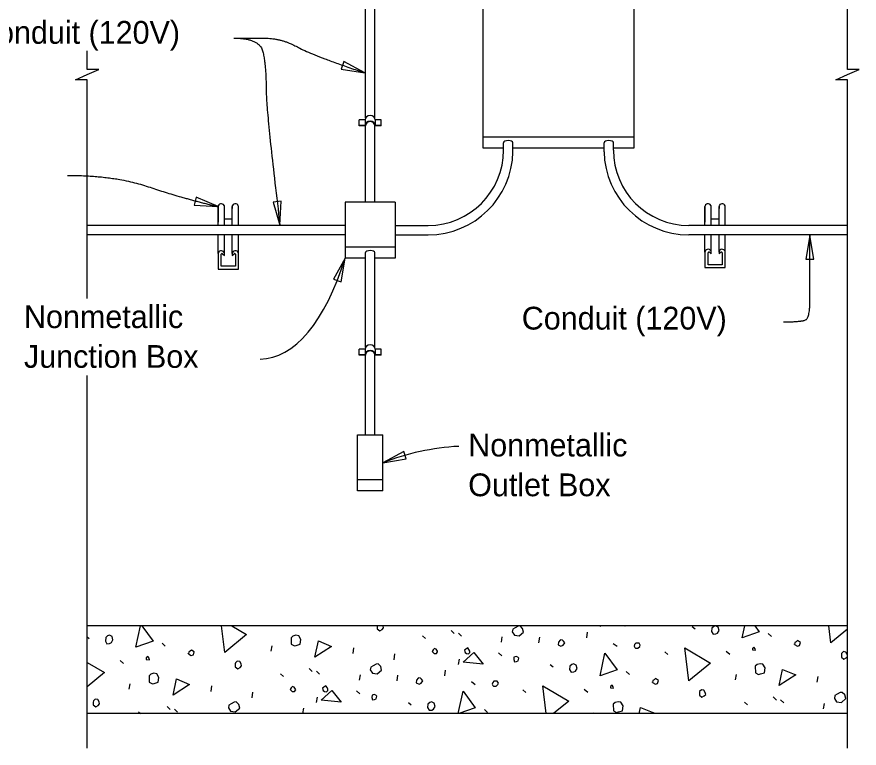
# Model space of a CAD drawing. Extents: x 0 to 30.8, y 0 to 21.2.
# Drawn here: x 12.47 to 18.06, y 9.96 to 14.82 of the extents above; entities that cross this region are included whole.
import ezdxf

# ---------------------------------------------------------------- set-up
doc = ezdxf.new("R2010")
doc.units = 0
for name, color, linetype in [('Dimension', 7, 'Continuous'), ('Lighting', 7, 'Continuous'), ('Miscellaneous', 7, 'Continuous'), ('SteelGirder', 7, 'Continuous'), ('SupstrConc', 7, 'Continuous'), ('TextStructures', 7, 'Continuous')]:
    doc.layers.add(name, color=color, linetype=linetype)

msp = doc.modelspace()

# ---------------------------------------------------------------- linework, layer by layer
at = {"layer": 'Dimension'}
for points in [[(17.9781, 9.9617), (17.9781, 14.3999), (17.9006, 14.3999), (17.9781, 14.4336), (18.0556, 14.4674), (17.9781, 14.4674), (17.9781, 15.572)], [(12.9354, 12.948), (12.9354, 14.3999), (12.8579, 14.3999), (12.9354, 14.4336), (13.0129, 14.4674), (12.9354, 14.4674), (12.9354, 14.5923)], [(12.9354, 9.9617), (12.9354, 12.4363)]]:
    msp.add_lwpolyline(points, dxfattribs=at)
for points in [[(14.7758, 14.445), (14.6363, 14.5201), (14.6193, 14.47)], [(13.8029, 13.5573), (13.6569, 13.6189), (13.6448, 13.5674)], [(14.2135, 13.4344), (14.2209, 13.5927), (14.1684, 13.5863)], [(17.7287, 13.3648), (17.7022, 13.2086), (17.7552, 13.2086)], [(14.6453, 13.2147), (14.5696, 13.0756), (14.6197, 13.0584)], [(14.8953, 11.8557), (15.0516, 11.8817), (15.0343, 11.9317)]]:
    msp.add_lwpolyline(points, close=True, dxfattribs=at)
msp.add_arc((15.4848, 10.3618), 1.606, 93.0575, 111.5329, dxfattribs=at)
msp.add_ellipse((14.0803, 14.1233), major_axis=(-0.0019, 1.5782), ratio=0.437101, start_param=3.141566, end_param=4.098452, dxfattribs=at)
for points in [[(13.9084, 14.676), (14.0798, 14.676), (14.1216, 14.492), (14.1216, 14.1911), (14.2135, 13.4344)], [(13.9084, 14.676), (13.992, 14.676), (14.2219, 14.676), (14.4267, 14.5631), (14.7758, 14.445)], [(12.8048, 13.7647), (13.1183, 13.7647), (13.5572, 13.6152), (13.8029, 13.5573)], [(17.5527, 12.792), (17.6791, 12.792), (17.7287, 12.8218), (17.7287, 13.0474), (17.7287, 13.3648)]]:
    msp.add_open_spline(points, degree=2, dxfattribs=at)
at = {"layer": 'Lighting'}
for p, q in [((14.7808, 14.1436), (14.7808, 14.9071)), ((14.8432, 14.1436), (14.8432, 14.9071)), ((14.7808, 13.5874), (14.7808, 14.0938)), ((14.8432, 13.5874), (14.8432, 14.0938)), ((16.5611, 14.0188), (15.5611, 14.0188)), ((15.6966, 13.9324), (15.6966, 13.9817)), ((15.759, 13.9218), (15.759, 13.9817)), ((16.3632, 13.9218), (16.3632, 13.9817)), ((16.4256, 13.9324), (16.4256, 13.9817)), ((14.6453, 13.5874), (14.6453, 13.2148)), ((14.9787, 13.5874), (14.6453, 13.5874)), ((14.9787, 13.5874), (14.9787, 13.2148)), ((13.8029, 13.4323), (13.8029, 13.5573)), ((13.8029, 13.5573), (13.8029, 13.4547)), ((13.8445, 13.5616), (13.8423, 13.5655)), ((13.8445, 13.5456), (13.8445, 13.5616)), ((13.8445, 13.4323), (13.8445, 13.5573)), ((13.8988, 13.5655), (13.8967, 13.5616)), ((13.8967, 13.5616), (13.8967, 13.5456)), ((13.8967, 13.4323), (13.8967, 13.5573)), ((13.9383, 13.4323), (13.9383, 13.5573)), ((17.0324, 13.4323), (17.0324, 13.5573)), ((17.0324, 13.5573), (17.0324, 13.4547)), ((17.074, 13.5616), (17.0719, 13.5655)), ((17.074, 13.5456), (17.074, 13.5616)), ((17.074, 13.4323), (17.074, 13.5573)), ((17.1284, 13.5655), (17.1262, 13.5616)), ((17.1262, 13.5616), (17.1262, 13.5456)), ((17.1262, 13.4323), (17.1262, 13.5573)), ((17.1678, 13.4323), (17.1678, 13.5573)), ((13.8967, 13.4733), (13.8445, 13.4733)), ((17.1262, 13.4733), (17.074, 13.4733)), ((14.6453, 13.4323), (12.9354, 13.4323)), ((14.9787, 13.4323), (15.1966, 13.4323)), ((17.9781, 13.4323), (16.9256, 13.4323)), ((14.6453, 13.3699), (12.9354, 13.3699)), ((13.8029, 13.2449), (13.8029, 13.3699)), ((13.8445, 13.2449), (13.8445, 13.3699)), ((13.8967, 13.2449), (13.8967, 13.3699)), ((13.9383, 13.2449), (13.9383, 13.3699)), ((14.9787, 13.3699), (15.1966, 13.3699)), ((17.9781, 13.3699), (16.9256, 13.3699)), ((17.0324, 13.2552), (17.0324, 13.3699)), ((17.074, 13.2552), (17.074, 13.3699)), ((17.1262, 13.2552), (17.1262, 13.3699)), ((17.1678, 13.2552), (17.1678, 13.3699)), ((13.8029, 13.2449), (13.8029, 13.1423)), ((13.8325, 13.2439), (13.8445, 13.2332)), ((13.8445, 13.2492), (13.8423, 13.2531)), ((13.8445, 13.2332), (13.8445, 13.2492)), ((13.8988, 13.2531), (13.8967, 13.2492)), ((13.8967, 13.2492), (13.8967, 13.2332)), ((13.8967, 13.2332), (13.9086, 13.2439)), ((13.9383, 13.1423), (13.9383, 13.2449)), ((14.9787, 13.289), (14.6453, 13.289)), ((14.7808, 12.6214), (14.7808, 13.2519)), ((14.8432, 12.6214), (14.8432, 13.2519)), ((17.0324, 13.2552), (17.0324, 13.1526)), ((17.0532, 13.1712), (17.0532, 13.2509)), ((17.0621, 13.2542), (17.074, 13.2435)), ((17.074, 13.2595), (17.0719, 13.2634)), ((17.074, 13.2435), (17.074, 13.2595)), ((17.1284, 13.2634), (17.1262, 13.2595)), ((17.1262, 13.2595), (17.1262, 13.2435)), ((17.1262, 13.2435), (17.1382, 13.2542)), ((17.147, 13.2509), (17.147, 13.1712)), ((17.1678, 13.1526), (17.1678, 13.2552)), ((13.8237, 13.1609), (13.8237, 13.2406)), ((13.9175, 13.2406), (13.9175, 13.1609)), ((14.7808, 13.2148), (14.6453, 13.2148)), ((14.9787, 13.2148), (14.8432, 13.2148)), ((13.8029, 13.1423), (13.9383, 13.1423)), ((13.9175, 13.1609), (13.8237, 13.1609)), ((17.0324, 13.1526), (17.1678, 13.1526)), ((17.147, 13.1712), (17.0532, 13.1712)), ((14.7808, 12.042), (14.7808, 12.5717)), ((14.8432, 12.042), (14.8432, 12.5717)), ((14.7287, 11.6695), (14.7287, 12.042)), ((14.7287, 12.042), (14.8953, 12.042)), ((14.8953, 11.6695), (14.8953, 12.042)), ((14.8953, 11.7437), (14.7287, 11.7437)), ((14.8953, 11.6695), (14.7287, 11.6695))]:
    msp.add_line(p, q, dxfattribs=at)
for points in [[(15.6966, 13.9446), (15.5611, 13.9446), (15.5611, 16.6696), (16.5611, 16.6696), (16.5611, 13.9446), (16.4256, 13.9446)], [(16.3632, 13.9446), (15.759, 13.9446)]]:
    msp.add_lwpolyline(points, dxfattribs=at)
for centre, radius, start, end in [((15.1966, 13.9324), 0.5, 270, 360), ((15.1966, 13.9324), 0.5625, 270, 358.9196), ((16.9256, 13.9324), 0.5625, 181.0804, 270), ((16.9256, 13.9324), 0.5, 180, 270)]:
    msp.add_arc(centre, radius, start, end, dxfattribs=at)
for centre, major_axis, ratio, start_param, end_param in [((15.7278, 13.9817), (-0.0312, 0), 0.446008, 3.14248, 6.283159), ((16.3944, 13.9817), (-0.0312, 0), 0.446008, 3.141619, 6.282298), ((13.8237, 13.5573), (-0.0208, 0), 0.8951, 3.598509, 6.283184), ((13.9175, 13.5573), (0.0208, 0), 0.8951, 0.000002, 2.684677), ((17.0532, 13.5573), (-0.0208, 0), 0.8951, 3.598509, 6.283184), ((17.147, 13.5573), (0.0208, 0), 0.8951, 0.000002, 2.684677), ((13.8237, 13.2449), (-0.0208, 0), 0.8951, 3.598509, 6.283184), ((13.8289, 13.2406), (-0.0052, 0), 0.8951, 3.926991, 6.283185), ((13.9175, 13.2449), (0.0208, 0), 0.8951, 0.000002, 2.684677), ((13.9123, 13.2406), (0.0052, 0), 0.8951, 6.283185, 8.63938), ((14.812, 13.2519), (-0.0312, 0), 0.446008, 3.14248, 6.283159), ((17.0532, 13.2552), (-0.0208, 0), 0.8951, 3.598509, 6.283184), ((17.0584, 13.2509), (-0.0052, 0), 0.8951, 3.926991, 6.283185), ((17.147, 13.2552), (0.0208, 0), 0.8951, 0.000002, 2.684677), ((17.1418, 13.2509), (0.0052, 0), 0.8951, 6.283185, 8.63938)]:
    msp.add_ellipse(centre, major_axis=major_axis, ratio=ratio, start_param=start_param, end_param=end_param, dxfattribs=at)
at = {"layer": 'Miscellaneous'}
for p, q in [((13.7054, 10.7741), (13.7073, 10.7724)), ((15.3482, 10.7436), (15.3691, 10.7233)), ((16.2489, 10.6951), (16.2544, 10.7327)), ((16.3405, 10.7688), (16.3414, 10.7741)), ((16.9487, 10.7687), (16.9684, 10.7532)), ((12.9354, 10.7001), (12.9476, 10.6905)), ((15.1584, 10.7082), (15.1787, 10.6904)), ((15.397, 10.7256), (15.418, 10.7053)), ((15.6824, 10.6649), (15.6885, 10.7002)), ((15.9317, 10.6618), (15.9372, 10.6995)), ((17.4528, 10.7226), (17.4738, 10.7023)), ((13.4321, 10.6598), (13.453, 10.6395)), ((14.1558, 10.6053), (14.1619, 10.6405)), ((14.6982, 10.5901), (14.7037, 10.6278)), ((16.4248, 10.6568), (16.4506, 10.6378)), ((14.9706, 10.5492), (14.976, 10.5869)), ((15.6624, 10.5948), (15.6858, 10.5752)), ((16.766, 10.6007), (16.7863, 10.5828)), ((17.1734, 10.6063), (17.1968, 10.5867)), ((13.1526, 10.5435), (13.176, 10.5239)), ((15.3987, 10.5164), (15.4048, 10.5517)), ((16.0069, 10.5163), (16.0266, 10.5009)), ((14.2166, 10.4559), (14.2369, 10.438)), ((14.4064, 10.4912), (14.4274, 10.471)), ((14.4552, 10.4732), (14.4762, 10.453)), ((15.3071, 10.4427), (15.3126, 10.4804)), ((16.511, 10.4702), (16.532, 10.45)), ((17.2348, 10.4157), (17.2409, 10.451)), ((14.7406, 10.4126), (14.7467, 10.4478)), ((14.9899, 10.4095), (14.9954, 10.4472)), ((15.4831, 10.4044), (15.5088, 10.3855)), ((17.7772, 10.4006), (17.7827, 10.4383)), ((13.2141, 10.3529), (13.2201, 10.3882)), ((13.7565, 10.3378), (13.7619, 10.3755)), ((14.7206, 10.3425), (14.744, 10.3229)), ((15.8242, 10.3483), (15.8445, 10.3305)), ((16.2316, 10.3539), (16.255, 10.3343)), ((14.0288, 10.2969), (14.0343, 10.3346)), ((14.4569, 10.2641), (14.463, 10.2993)), ((17.4854, 10.3017), (17.5063, 10.2814)), ((17.5342, 10.2837), (17.5552, 10.2634)), ((13.4646, 10.2389), (13.4856, 10.2186)), ((14.3654, 10.1908), (14.3708, 10.228)), ((15.0652, 10.264), (15.0848, 10.2485)), ((17.2956, 10.2663), (17.3159, 10.2485)), ((17.8196, 10.223), (17.8257, 10.2583)), ((13.2748, 10.2035), (13.2893, 10.1908)), ((13.5134, 10.2209), (13.5344, 10.2006)), ((13.8041, 10.1908), (13.8049, 10.1955)), ((14.053, 10.1908), (14.0536, 10.1948)), ((15.5693, 10.2179), (15.5902, 10.1976)), ((16.2978, 10.1908), (16.2991, 10.1986))]:
    msp.add_line(p, q, dxfattribs=at)
for points in [[(13.2585, 10.6314), (13.2888, 10.7741)], [(13.2966, 10.7741), (13.3718, 10.6721), (13.2585, 10.6314)], [(13.8473, 10.5976), (13.8249, 10.7741)], [(13.8937, 10.7741), (13.9915, 10.7165), (13.8473, 10.5976)], [(14.8589, 10.7729), (14.8586, 10.7547), (14.8752, 10.7411), (14.8908, 10.7504), (14.901, 10.7609), (14.8977, 10.773), (14.8971, 10.7741)], [(14.859, 10.7741), (14.8589, 10.7729)], [(15.7547, 10.7334), (15.7684, 10.7112), (15.8006, 10.7069), (15.8299, 10.7329), (15.8234, 10.757), (15.8061, 10.7731), (15.7934, 10.7723), (15.773, 10.7616), (15.7574, 10.7523), (15.7547, 10.7334)], [(16.5004, 10.7741), (16.503, 10.7709), (16.4714, 10.7741)], [(17.078, 10.7593), (17.0766, 10.7357), (17.0866, 10.7176), (17.1042, 10.7197), (17.1156, 10.7254), (17.1262, 10.7438), (17.1204, 10.7655), (17.1027, 10.7737), (17.0906, 10.7705), (17.078, 10.7593)], [(17.2793, 10.6942), (17.2962, 10.7741)], [(17.3637, 10.7741), (17.3926, 10.7349), (17.2793, 10.6942)], [(17.8681, 10.6604), (17.8536, 10.7741)], [(17.9781, 10.7512), (17.8681, 10.6604)], [(13.0573, 10.6965), (13.0559, 10.6729), (13.0659, 10.6548), (13.0834, 10.657), (13.0949, 10.6626), (13.1055, 10.681), (13.0996, 10.7027), (13.0819, 10.7109), (13.0698, 10.7077), (13.0573, 10.6965)], [(14.2871, 10.6948), (14.2885, 10.6512), (14.3093, 10.6412), (14.3213, 10.6444), (14.3479, 10.6515), (14.3522, 10.6838), (14.3379, 10.7084), (14.319, 10.7111), (14.2997, 10.7059), (14.2871, 10.6948)], [(14.4458, 10.5665), (14.4688, 10.6736), (14.5562, 10.6375), (14.4458, 10.5665)], [(16.0602, 10.6652), (16.0599, 10.647), (16.0776, 10.6388), (16.0915, 10.6451), (16.1027, 10.6611), (16.0947, 10.6718), (16.0879, 10.6778), (16.077, 10.68), (16.0721, 10.6787), (16.0602, 10.6652)], [(17.6275, 10.6503), (17.6458, 10.6397), (17.6603, 10.6436), (17.6655, 10.6631), (17.6464, 10.6761), (17.6381, 10.6687), (17.6291, 10.6637), (17.6275, 10.6503), (17.6262, 10.6552)], [(15.2226, 10.6038), (15.2368, 10.5895), (15.2519, 10.591), (15.2596, 10.6008), (15.2583, 10.6056), (15.2496, 10.6188), (15.238, 10.6235), (15.2303, 10.6136), (15.2226, 10.6038)], [(15.4416, 10.5978), (15.4514, 10.5901), (15.4648, 10.5885), (15.4732, 10.5959), (15.473, 10.6062), (15.4673, 10.6176), (15.4593, 10.6284), (15.4461, 10.6197), (15.4377, 10.6123), (15.4416, 10.5978)], [(16.5666, 10.63), (16.5727, 10.6265), (16.5885, 10.6256), (16.601, 10.6367), (16.6039, 10.6452), (16.5952, 10.6584), (16.5746, 10.6581), (16.5662, 10.6507), (16.564, 10.6397), (16.5666, 10.63)], [(16.9263, 10.4081), (16.8983, 10.6284), (17.0704, 10.5269), (16.9263, 10.4081)], [(17.3473, 10.6141), (17.3686, 10.612), (17.366, 10.6217), (17.3579, 10.6324), (17.3471, 10.6244), (17.3473, 10.6141)], [(13.3266, 10.5513), (13.3478, 10.5492), (13.3452, 10.5589), (13.3372, 10.5697), (13.3264, 10.5616), (13.3266, 10.5513)], [(13.6067, 10.5875), (13.6251, 10.5769), (13.6396, 10.5808), (13.6447, 10.6003), (13.6257, 10.6133), (13.6173, 10.6059), (13.6083, 10.6009), (13.6067, 10.5875), (13.6054, 10.5924)], [(15.4281, 10.5321), (15.4986, 10.5975), (15.5612, 10.5185), (15.4281, 10.5321)], [(15.765, 10.5499), (15.7689, 10.5354), (15.7816, 10.5362), (15.793, 10.5418), (15.7988, 10.5589), (15.7921, 10.5649), (15.7805, 10.5695), (15.766, 10.5656), (15.765, 10.5499)], [(16.3375, 10.4418), (16.3695, 10.5928), (16.4508, 10.4826), (16.3375, 10.4418)], [(17.9379, 10.5834), (17.9376, 10.5652), (17.9542, 10.5515), (17.9698, 10.5609), (17.9781, 10.5695)], [(17.9781, 10.5781), (17.9767, 10.5834), (17.9673, 10.599), (17.9509, 10.6024), (17.9384, 10.5913), (17.9379, 10.5834)], [(12.9354, 10.5315), (13.0497, 10.4642), (12.9354, 10.3699)], [(13.9171, 10.5206), (13.9168, 10.5024), (13.9334, 10.4887), (13.949, 10.4981), (13.9592, 10.5086), (13.9559, 10.5206), (13.9466, 10.5362), (13.9301, 10.5396), (13.9176, 10.5285), (13.9171, 10.5206)], [(14.8129, 10.4811), (14.8266, 10.4589), (14.8588, 10.4546), (14.8881, 10.4805), (14.8816, 10.5047), (14.8644, 10.5208), (14.8516, 10.5199), (14.8312, 10.5093), (14.8156, 10.4999), (14.8129, 10.4811)], [(16.1363, 10.507), (16.1348, 10.4833), (16.1448, 10.4653), (16.1624, 10.4674), (16.1738, 10.473), (16.1844, 10.4914), (16.1786, 10.5132), (16.1609, 10.5213), (16.1488, 10.5181), (16.1363, 10.507)], [(17.3661, 10.5052), (17.3675, 10.4616), (17.3882, 10.4516), (17.4003, 10.4549), (17.4269, 10.462), (17.4312, 10.4942), (17.4168, 10.5188), (17.398, 10.5215), (17.3787, 10.5164), (17.3661, 10.5052)], [(13.3454, 10.4424), (13.3467, 10.3988), (13.3675, 10.3888), (13.3796, 10.3921), (13.4061, 10.3992), (13.4104, 10.4314), (13.3961, 10.456), (13.3772, 10.4588), (13.3579, 10.4536), (13.3454, 10.4424)], [(17.5247, 10.3769), (17.5478, 10.484), (17.6351, 10.4479), (17.5247, 10.3769)], [(13.504, 10.3141), (13.527, 10.4212), (13.6144, 10.3851), (13.504, 10.3141)], [(15.1184, 10.4128), (15.1181, 10.3946), (15.1359, 10.3865), (15.1497, 10.3928), (15.161, 10.4087), (15.1529, 10.4195), (15.1461, 10.4254), (15.1352, 10.4277), (15.1303, 10.4264), (15.1184, 10.4128)], [(15.6248, 10.3777), (15.6309, 10.3742), (15.6467, 10.3732), (15.6593, 10.3843), (15.6621, 10.3929), (15.6534, 10.4061), (15.6328, 10.4057), (15.6245, 10.3983), (15.6222, 10.3874), (15.6248, 10.3777)], [(16.6857, 10.398), (16.7041, 10.3874), (16.7186, 10.3912), (16.7237, 10.4107), (16.7047, 10.4238), (16.6963, 10.4163), (16.6873, 10.4113), (16.6857, 10.398), (16.6844, 10.4028)], [(14.2808, 10.3515), (14.295, 10.3371), (14.3101, 10.3386), (14.3178, 10.3484), (14.3165, 10.3533), (14.3078, 10.3665), (14.2962, 10.3711), (14.2885, 10.3613), (14.2808, 10.3515)], [(14.4864, 10.2797), (14.5568, 10.3452), (14.6194, 10.2662), (14.4864, 10.2797)], [(14.4998, 10.3454), (14.5096, 10.3377), (14.523, 10.3361), (14.5314, 10.3435), (14.5312, 10.3538), (14.5256, 10.3653), (14.5175, 10.3761), (14.5043, 10.3673), (14.4959, 10.3599), (14.4998, 10.3454)], [(15.396, 10.1908), (15.4277, 10.3404), (15.509, 10.2302), (15.3993, 10.1908)], [(15.9801, 10.1908), (15.9565, 10.376), (16.1287, 10.2746), (16.027, 10.1908)], [(16.4055, 10.3617), (16.4268, 10.3597), (16.4242, 10.3693), (16.4161, 10.3801), (16.4054, 10.372), (16.4055, 10.3617)], [(16.9961, 10.331), (16.9958, 10.3128), (17.0124, 10.2992), (17.028, 10.3085), (17.0381, 10.319), (17.0349, 10.3311), (17.0256, 10.3467), (17.0091, 10.35), (16.9966, 10.3389), (16.9961, 10.331)], [(12.9753, 10.2682), (12.975, 10.25), (12.9917, 10.2364), (13.0073, 10.2457), (13.0174, 10.2562), (13.0142, 10.2683), (13.0048, 10.2839), (12.9884, 10.2873), (12.9758, 10.2761), (12.9753, 10.2682)], [(14.8232, 10.2975), (14.8271, 10.283), (14.8398, 10.2838), (14.8513, 10.2895), (14.857, 10.3066), (14.8503, 10.3125), (14.8387, 10.3172), (14.8242, 10.3133), (14.8232, 10.2975)], [(17.8919, 10.2915), (17.9056, 10.2693), (17.9378, 10.265), (17.9671, 10.291), (17.9606, 10.3151), (17.9433, 10.3312), (17.9306, 10.3304), (17.9102, 10.3197), (17.8946, 10.3104), (17.8919, 10.2915)], [(13.8711, 10.2287), (13.8848, 10.2065), (13.917, 10.2022), (13.9463, 10.2282), (13.9398, 10.2523), (13.9226, 10.2684), (13.9099, 10.2676), (13.8894, 10.2569), (13.8738, 10.2476), (13.8711, 10.2287)], [(15.1945, 10.2546), (15.1931, 10.231), (15.2031, 10.2129), (15.2206, 10.215), (15.232, 10.2207), (15.2427, 10.2391), (15.2368, 10.2608), (15.2191, 10.269), (15.207, 10.2658), (15.1945, 10.2546)], [(16.4243, 10.2529), (16.4257, 10.2092), (16.4465, 10.1993), (16.4585, 10.2025), (16.4851, 10.2096), (16.4894, 10.2419), (16.4751, 10.2665), (16.4562, 10.2692), (16.4369, 10.264), (16.4243, 10.2529)], [(16.5972, 10.1908), (16.606, 10.2317), (16.6933, 10.1956), (16.6859, 10.1908)]]:
    msp.add_lwpolyline(points, dxfattribs=at)
at = {"layer": 'SteelGirder'}
for p, q in [((14.7785, 14.1334), (14.7391, 14.1334)), ((14.7391, 14.0938), (14.7391, 14.1334)), ((14.7785, 14.0961), (14.7391, 14.0961)), ((14.7808, 14.0938), (14.7391, 14.0938)), ((14.7785, 14.1335), (14.7785, 14.0961)), ((14.8849, 14.0938), (14.8432, 14.0938)), ((14.8849, 14.1334), (14.8455, 14.1334)), ((14.8455, 14.1334), (14.8455, 14.0961)), ((14.8849, 14.0961), (14.8455, 14.0961)), ((14.8849, 14.0938), (14.8849, 14.1334)), ((14.7785, 12.6113), (14.7391, 12.6113)), ((14.7391, 12.5717), (14.7391, 12.6113)), ((14.7785, 12.574), (14.7391, 12.574)), ((14.7785, 12.6113), (14.7785, 12.574)), ((14.8849, 12.6113), (14.8455, 12.6113)), ((14.8455, 12.6113), (14.8455, 12.574)), ((14.8849, 12.574), (14.8455, 12.574)), ((14.8849, 12.5717), (14.8849, 12.6113)), ((14.7808, 12.5717), (14.7391, 12.5717)), ((14.8849, 12.5717), (14.8432, 12.5717))]:
    msp.add_line(p, q, dxfattribs=at)
for centre, major_axis, ratio, end_param in [((14.812, 14.1334), (-0.0335, 0), 0.830773, 6.282753), ((14.812, 14.0961), (-0.0335, 0), 0.830773, 6.282753), ((14.812, 14.0938), (-0.0312, 0), 0.892016, 6.283768), ((14.812, 12.6113), (-0.0335, 0), 0.830773, 6.282753), ((14.812, 12.574), (-0.0335, 0), 0.830773, 6.282753), ((14.812, 12.5717), (-0.0312, 0), 0.892016, 6.283768)]:
    msp.add_ellipse(centre, major_axis=major_axis, ratio=ratio, start_param=3.141593, end_param=end_param, dxfattribs=at)
at = {"layer": 'SupstrConc'}
for p, q in [((17.9781, 10.7741), (12.9354, 10.7741)), ((17.9781, 10.1908), (12.9354, 10.1908))]:
    msp.add_line(p, q, dxfattribs=at)

# ---------------------------------------------------------------- texts
at = {"layer": 'Dimension'}
for s, p in [('Nonmetallic', (12.5154, 12.7509)), ('Junction Box', (12.5154, 12.4869))]:
    msp.add_text(s, height=0.1512, dxfattribs=at).set_placement(p)
at = {"layer": 'TextStructures'}
for s, p in [('Conduit (120V)', (12.1906, 14.6384)), ('Conduit (120V)', (15.8176, 12.741)), ('Nonmetallic ', (15.4623, 11.8984)), ('Outlet Box', (15.4623, 11.6344))]:
    msp.add_text(s, height=0.1512, dxfattribs=at).set_placement(p)

doc.saveas('drawing.dxf')
